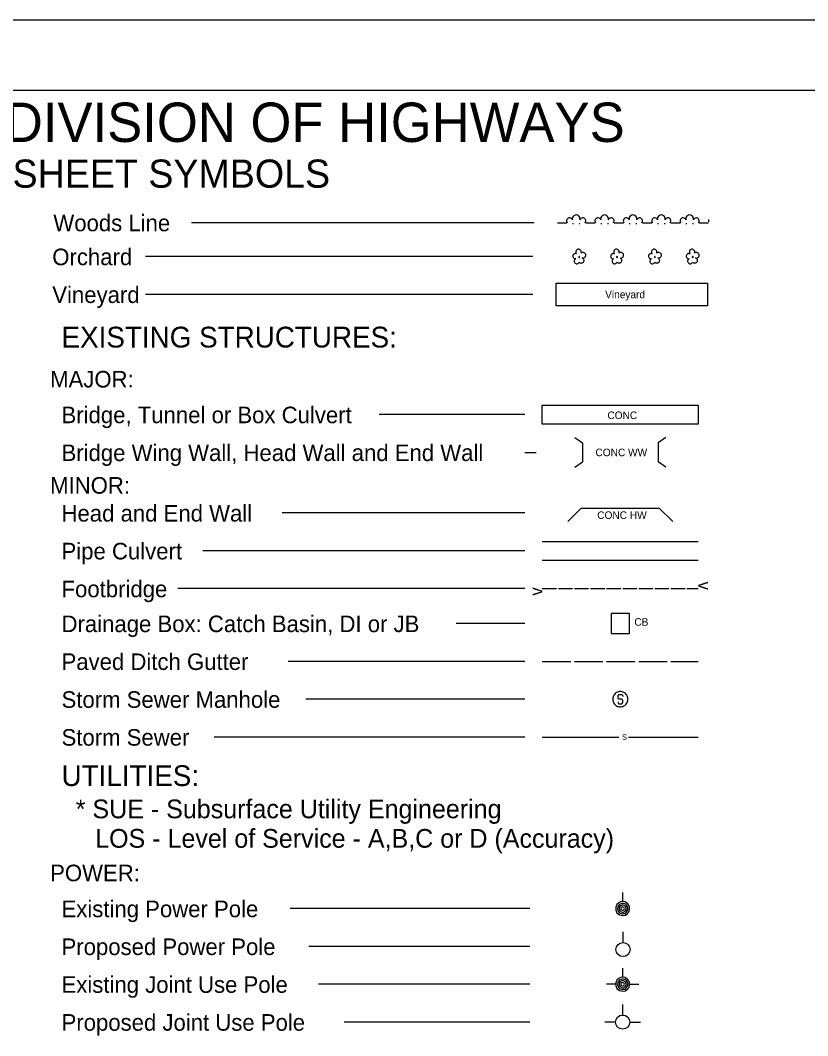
# Model space of a CAD drawing. Extents: x 2040834 to 2047174, y 618431 to 621625.
# Drawn here: x 2046085 to 2046575, y 620993 to 621625 of the extents above; entities that cross this region are included whole.
import ezdxf

# ---------------------------------------------------------------- set-up
doc = ezdxf.new("R2010")
doc.units = 0
doc.layers.add('Default', color=7, linetype='Continuous')

msp = doc.modelspace()

# ---------------------------------------------------------------- linework, layer by layer
at = {"layer": 'Default'}
for p, q in [((2047057.71, 621624.54), (2045074.38, 621624.54)), ((2047013.96, 621580.79), (2045118.13, 621580.79)), ((2046404.35, 621498.62), (2046191.15, 621498.62)), ((2046418.94, 621498.62), (2046424.82, 621498.62)), ((2046428.29, 621498.03), (2046428.88, 621498.03)), ((2046432.41, 621498.03), (2046433, 621498.03)), ((2046436.59, 621498.62), (2046442.48, 621498.62)), ((2046445.95, 621498.03), (2046446.54, 621498.03)), ((2046450.07, 621498.03), (2046450.66, 621498.03)), ((2046454.25, 621498.62), (2046460.13, 621498.62)), ((2046463.61, 621498.03), (2046464.2, 621498.03)), ((2046467.73, 621498.03), (2046468.32, 621498.03)), ((2046471.91, 621498.62), (2046477.79, 621498.62)), ((2046481.26, 621498.03), (2046481.85, 621498.03)), ((2046485.38, 621498.03), (2046485.97, 621498.03)), ((2046489.56, 621498.62), (2046495.45, 621498.62)), ((2046498.92, 621498.03), (2046499.51, 621498.03)), ((2046503.04, 621498.03), (2046503.63, 621498.03)), ((2046507.22, 621498.62), (2046513.1, 621498.62)), ((2046403.68, 621477.52), (2046162.45, 621477.52)), ((2046403.68, 621453.97), (2046162.45, 621453.97)), ((2046398.6, 621379.22), (2046308.01, 621379.22)), ((2046429.74, 621364.93), (2046434.56, 621361.56)), ((2046486.47, 621364.93), (2046481.65, 621361.56)), ((2046434.56, 621361.56), (2046434.56, 621349.79)), ((2046481.65, 621361.56), (2046481.65, 621349.79)), ((2046398.6, 621355.68), (2046405.65, 621355.68)), ((2046429.74, 621346.42), (2046434.56, 621349.79)), ((2046486.47, 621346.42), (2046481.65, 621349.79)), ((2046425.5, 621312.63), (2046433.83, 621320.96)), ((2046433.83, 621320.96), (2046482.38, 621320.96)), ((2046482.38, 621320.96), (2046490.71, 621312.63)), ((2046398.6, 621318.02), (2046247.58, 621318.02)), ((2046409.55, 621300.36), (2046506.66, 621300.36)), ((2046398.6, 621294.48), (2046198.28, 621294.48)), ((2046409.55, 621288.59), (2046506.66, 621288.59)), ((2046398.6, 621270.94), (2046182.64, 621270.94)), ((2046409.55, 621270.94), (2046418.38, 621270.94)), ((2046419.56, 621270.94), (2046428.38, 621270.94)), ((2046429.56, 621270.94), (2046438.39, 621270.94)), ((2046439.57, 621270.94), (2046448.4, 621270.94)), ((2046449.57, 621270.94), (2046458.4, 621270.94)), ((2046459.58, 621270.94), (2046468.41, 621270.94)), ((2046469.58, 621270.94), (2046478.41, 621270.94)), ((2046479.59, 621270.94), (2046488.42, 621270.94)), ((2046489.59, 621270.94), (2046498.42, 621270.94)), ((2046499.6, 621270.94), (2046506.66, 621270.94)), ((2046398.6, 621249.23), (2046355.88, 621249.23)), ((2046398.6, 621225.69), (2046251.25, 621225.69)), ((2046409.55, 621225.69), (2046427.21, 621225.69)), ((2046429.56, 621225.69), (2046447.22, 621225.69)), ((2046449.57, 621225.69), (2046467.23, 621225.69)), ((2046469.58, 621225.69), (2046487.24, 621225.69)), ((2046489.59, 621225.69), (2046506.66, 621225.69)), ((2046457.53, 621205.09), (2046458.79, 621205.09)), ((2046398.6, 621202.15), (2046262.44, 621202.15)), ((2046456.69, 621202.99), (2046456.69, 621204.25)), ((2046456.69, 621200.51), (2046456.69, 621200.08)), ((2046458.79, 621202.19), (2046457.53, 621202.19)), ((2046457.53, 621199.28), (2046458.79, 621199.28)), ((2046459.6, 621204.25), (2046459.6, 621203.83)), ((2046459.6, 621200.08), (2046459.6, 621201.38)), ((2046398.6, 621178.61), (2046205.33, 621178.61)), ((2046409.55, 621178.61), (2046457.25, 621178.61)), ((2046463.14, 621178.61), (2046506.66, 621178.61)), ((2046459.58, 621076.21), (2046459.58, 621081.86)), ((2046401.89, 621071.87), (2046252.55, 621071.87)), ((2046459.83, 621050.81), (2046459.83, 621057.43)), ((2046401.89, 621048.33), (2046264.19, 621048.33)), ((2046459.58, 621029.13), (2046459.58, 621034.78)), ((2046401.89, 621024.78), (2046270.15, 621024.78)), ((2046455.23, 621024.78), (2046449.58, 621024.78)), ((2046463.92, 621024.78), (2046469.57, 621024.78)), ((2046459.58, 621005.67), (2046459.58, 621012.29)), ((2046401.89, 621001.24), (2046286.27, 621001.24)), ((2046455.16, 621001.26), (2046448.54, 621001.26)), ((2046463.99, 621001.26), (2046470.61, 621001.26))]:
    msp.add_line(p, q, dxfattribs=at)
for points in [[(2046433.63, 621479.58), (2046433.81, 621479.93), (2046433.87, 621480.28), (2046433.81, 621480.63), (2046433.75, 621480.99), (2046433.57, 621481.28), (2046433.4, 621481.58), (2046433.1, 621481.81), (2046432.81, 621481.99), (2046432.4, 621482.11), (2046432.1, 621482.11), (2046431.75, 621482.05), (2046431.4, 621481.93), (2046431.1, 621481.75), (2046430.81, 621481.52), (2046430.63, 621481.16), (2046430.51, 621480.87), (2046430.45, 621480.52), (2046430.45, 621480.16), (2046430.51, 621479.81), (2046430.69, 621479.52), (2046430.92, 621479.16), (2046430.63, 621479.34), (2046430.28, 621479.4), (2046429.92, 621479.4), (2046429.63, 621479.28), (2046429.34, 621479.16), (2046429.04, 621478.93), (2046428.81, 621478.69), (2046428.63, 621478.4), (2046428.57, 621478.1), (2046428.51, 621477.69), (2046428.57, 621477.4), (2046428.69, 621477.1), (2046428.92, 621476.81), (2046429.1, 621476.57), (2046429.39, 621476.4), (2046429.75, 621476.22), (2046430.04, 621476.16), (2046430.4, 621476.16), (2046430.1, 621476.04), (2046429.81, 621475.81), (2046429.63, 621475.57), (2046429.51, 621475.22), (2046429.39, 621474.87), (2046429.39, 621474.57), (2046429.45, 621474.22), (2046429.63, 621473.93), (2046429.81, 621473.63), (2046430.04, 621473.4), (2046430.34, 621473.22), (2046430.63, 621473.1), (2046430.98, 621473.1), (2046431.34, 621473.1), (2046431.63, 621473.16), (2046431.93, 621473.4), (2046432.22, 621473.57), (2046432.51, 621474.1)], [(2046432.63, 621477.52), (2046432.46, 621477.52), (2046432.34, 621477.46), (2046432.22, 621477.4), (2046432.22, 621477.22), (2046432.22, 621477.1), (2046432.34, 621476.99), (2046432.51, 621476.99), (2046432.63, 621476.99), (2046432.75, 621477.1), (2046432.81, 621477.28), (2046432.75, 621477.4), (2046432.63, 621477.52)], [(2046432.51, 621474.1), (2046433.22, 621473.69), (2046433.57, 621473.57), (2046433.93, 621473.51), (2046434.28, 621473.57), (2046434.57, 621473.69), (2046434.87, 621473.87), (2046435.16, 621474.1), (2046435.34, 621474.4), (2046435.46, 621474.69), (2046435.57, 621475.04), (2046435.52, 621475.4), (2046435.46, 621475.75), (2046435.22, 621476.1), (2046435.04, 621476.34), (2046434.75, 621476.51), (2046434.4, 621476.69), (2046434.75, 621476.63), (2046435.16, 621476.63), (2046435.46, 621476.75), (2046435.81, 621476.93), (2046436.1, 621477.1), (2046436.34, 621477.4), (2046436.52, 621477.75), (2046436.57, 621478.1), (2046436.63, 621478.46), (2046436.57, 621478.81), (2046436.46, 621479.16), (2046436.22, 621479.46), (2046435.93, 621479.75), (2046435.63, 621479.93), (2046435.28, 621480.05), (2046434.93, 621480.11), (2046434.57, 621480.11), (2046434.22, 621479.99), (2046433.93, 621479.81), (2046433.63, 621479.58)], [(2046457.17, 621479.58), (2046457.35, 621479.93), (2046457.41, 621480.28), (2046457.35, 621480.63), (2046457.29, 621480.99), (2046457.12, 621481.28), (2046456.94, 621481.58), (2046456.64, 621481.81), (2046456.35, 621481.99), (2046455.94, 621482.11), (2046455.64, 621482.11), (2046455.29, 621482.05), (2046454.94, 621481.93), (2046454.64, 621481.75), (2046454.35, 621481.52), (2046454.17, 621481.16), (2046454.05, 621480.87), (2046454, 621480.52), (2046454, 621480.16), (2046454.05, 621479.81), (2046454.23, 621479.52), (2046454.47, 621479.16), (2046454.17, 621479.34), (2046453.82, 621479.4), (2046453.47, 621479.4), (2046453.17, 621479.28), (2046452.88, 621479.16), (2046452.58, 621478.93), (2046452.35, 621478.69), (2046452.17, 621478.4), (2046452.11, 621478.1), (2046452.05, 621477.69), (2046452.11, 621477.4), (2046452.23, 621477.1), (2046452.47, 621476.81), (2046452.64, 621476.57), (2046452.94, 621476.4), (2046453.29, 621476.22), (2046453.58, 621476.16), (2046453.94, 621476.16), (2046453.64, 621476.04), (2046453.35, 621475.81), (2046453.17, 621475.57), (2046453.05, 621475.22), (2046452.94, 621474.87), (2046452.94, 621474.57), (2046453, 621474.22), (2046453.17, 621473.93), (2046453.35, 621473.63), (2046453.58, 621473.4), (2046453.88, 621473.22), (2046454.17, 621473.1), (2046454.53, 621473.1), (2046454.88, 621473.1), (2046455.17, 621473.16), (2046455.47, 621473.4), (2046455.76, 621473.57), (2046456.06, 621474.1)], [(2046456.17, 621477.52), (2046456, 621477.52), (2046455.88, 621477.46), (2046455.76, 621477.4), (2046455.76, 621477.22), (2046455.76, 621477.1), (2046455.88, 621476.99), (2046456.06, 621476.99), (2046456.17, 621476.99), (2046456.29, 621477.1), (2046456.35, 621477.28), (2046456.29, 621477.4), (2046456.17, 621477.52)], [(2046456.06, 621474.1), (2046456.76, 621473.69), (2046457.12, 621473.57), (2046457.47, 621473.51), (2046457.82, 621473.57), (2046458.12, 621473.69), (2046458.41, 621473.87), (2046458.7, 621474.1), (2046458.88, 621474.4), (2046459, 621474.69), (2046459.12, 621475.04), (2046459.06, 621475.4), (2046459, 621475.75), (2046458.76, 621476.1), (2046458.59, 621476.34), (2046458.29, 621476.51), (2046457.94, 621476.69), (2046458.29, 621476.63), (2046458.7, 621476.63), (2046459, 621476.75), (2046459.35, 621476.93), (2046459.65, 621477.1), (2046459.88, 621477.4), (2046460.06, 621477.75), (2046460.12, 621478.1), (2046460.18, 621478.46), (2046460.12, 621478.81), (2046460, 621479.16), (2046459.76, 621479.46), (2046459.47, 621479.75), (2046459.18, 621479.93), (2046458.82, 621480.05), (2046458.47, 621480.11), (2046458.12, 621480.11), (2046457.76, 621479.99), (2046457.47, 621479.81), (2046457.17, 621479.58)], [(2046480.72, 621479.58), (2046480.89, 621479.93), (2046480.95, 621480.28), (2046480.89, 621480.63), (2046480.83, 621480.99), (2046480.66, 621481.28), (2046480.48, 621481.58), (2046480.19, 621481.81), (2046479.89, 621481.99), (2046479.48, 621482.11), (2046479.19, 621482.11), (2046478.83, 621482.05), (2046478.48, 621481.93), (2046478.19, 621481.75), (2046477.89, 621481.52), (2046477.71, 621481.16), (2046477.6, 621480.87), (2046477.54, 621480.52), (2046477.54, 621480.16), (2046477.6, 621479.81), (2046477.77, 621479.52), (2046478.01, 621479.16), (2046477.71, 621479.34), (2046477.36, 621479.4), (2046477.01, 621479.4), (2046476.71, 621479.28), (2046476.42, 621479.16), (2046476.13, 621478.93), (2046475.89, 621478.69), (2046475.71, 621478.4), (2046475.65, 621478.1), (2046475.6, 621477.69), (2046475.65, 621477.4), (2046475.77, 621477.1), (2046476.01, 621476.81), (2046476.18, 621476.57), (2046476.48, 621476.4), (2046476.83, 621476.22), (2046477.13, 621476.16), (2046477.48, 621476.16), (2046477.18, 621476.04), (2046476.89, 621475.81), (2046476.71, 621475.57), (2046476.6, 621475.22), (2046476.48, 621474.87), (2046476.48, 621474.57), (2046476.54, 621474.22), (2046476.71, 621473.93), (2046476.89, 621473.63), (2046477.13, 621473.4), (2046477.42, 621473.22), (2046477.71, 621473.1), (2046478.07, 621473.1), (2046478.42, 621473.1), (2046478.71, 621473.16), (2046479.01, 621473.4), (2046479.3, 621473.57), (2046479.6, 621474.1)], [(2046479.72, 621477.52), (2046479.54, 621477.52), (2046479.42, 621477.46), (2046479.3, 621477.4), (2046479.3, 621477.22), (2046479.3, 621477.1), (2046479.42, 621476.99), (2046479.6, 621476.99), (2046479.72, 621476.99), (2046479.83, 621477.1), (2046479.89, 621477.28), (2046479.83, 621477.4), (2046479.72, 621477.52)], [(2046479.6, 621474.1), (2046480.3, 621473.69), (2046480.66, 621473.57), (2046481.01, 621473.51), (2046481.36, 621473.57), (2046481.66, 621473.69), (2046481.95, 621473.87), (2046482.25, 621474.1), (2046482.42, 621474.4), (2046482.54, 621474.69), (2046482.66, 621475.04), (2046482.6, 621475.4), (2046482.54, 621475.75), (2046482.3, 621476.1), (2046482.13, 621476.34), (2046481.83, 621476.51), (2046481.48, 621476.69), (2046481.83, 621476.63), (2046482.25, 621476.63), (2046482.54, 621476.75), (2046482.89, 621476.93), (2046483.19, 621477.1), (2046483.42, 621477.4), (2046483.6, 621477.75), (2046483.66, 621478.1), (2046483.72, 621478.46), (2046483.66, 621478.81), (2046483.54, 621479.16), (2046483.31, 621479.46), (2046483.01, 621479.75), (2046482.72, 621479.93), (2046482.36, 621480.05), (2046482.01, 621480.11), (2046481.66, 621480.11), (2046481.3, 621479.99), (2046481.01, 621479.81), (2046480.72, 621479.58)], [(2046504.26, 621479.58), (2046504.43, 621479.93), (2046504.49, 621480.28), (2046504.43, 621480.63), (2046504.38, 621480.99), (2046504.2, 621481.28), (2046504.02, 621481.58), (2046503.73, 621481.81), (2046503.43, 621481.99), (2046503.02, 621482.11), (2046502.73, 621482.11), (2046502.37, 621482.05), (2046502.02, 621481.93), (2046501.73, 621481.75), (2046501.43, 621481.52), (2046501.26, 621481.16), (2046501.14, 621480.87), (2046501.08, 621480.52), (2046501.08, 621480.16), (2046501.14, 621479.81), (2046501.32, 621479.52), (2046501.55, 621479.16), (2046501.26, 621479.34), (2046500.9, 621479.4), (2046500.55, 621479.4), (2046500.26, 621479.28), (2046499.96, 621479.16), (2046499.67, 621478.93), (2046499.43, 621478.69), (2046499.26, 621478.4), (2046499.2, 621478.1), (2046499.14, 621477.69), (2046499.2, 621477.4), (2046499.31, 621477.1), (2046499.55, 621476.81), (2046499.73, 621476.57), (2046500.02, 621476.4), (2046500.37, 621476.22), (2046500.67, 621476.16), (2046501.02, 621476.16), (2046500.73, 621476.04), (2046500.43, 621475.81), (2046500.26, 621475.57), (2046500.14, 621475.22), (2046500.02, 621474.87), (2046500.02, 621474.57), (2046500.08, 621474.22), (2046500.26, 621473.93), (2046500.43, 621473.63), (2046500.67, 621473.4), (2046500.96, 621473.22), (2046501.26, 621473.1), (2046501.61, 621473.1), (2046501.96, 621473.1), (2046502.26, 621473.16), (2046502.55, 621473.4), (2046502.85, 621473.57), (2046503.14, 621474.1)], [(2046503.26, 621477.52), (2046503.08, 621477.52), (2046502.96, 621477.46), (2046502.85, 621477.4), (2046502.85, 621477.22), (2046502.85, 621477.1), (2046502.96, 621476.99), (2046503.14, 621476.99), (2046503.26, 621476.99), (2046503.37, 621477.1), (2046503.43, 621477.28), (2046503.37, 621477.4), (2046503.26, 621477.52)], [(2046503.14, 621474.1), (2046503.85, 621473.69), (2046504.2, 621473.57), (2046504.55, 621473.51), (2046504.91, 621473.57), (2046505.2, 621473.69), (2046505.49, 621473.87), (2046505.79, 621474.1), (2046505.96, 621474.4), (2046506.08, 621474.69), (2046506.2, 621475.04), (2046506.14, 621475.4), (2046506.08, 621475.75), (2046505.85, 621476.1), (2046505.67, 621476.34), (2046505.38, 621476.51), (2046505.02, 621476.69), (2046505.38, 621476.63), (2046505.79, 621476.63), (2046506.08, 621476.75), (2046506.44, 621476.93), (2046506.73, 621477.1), (2046506.97, 621477.4), (2046507.14, 621477.75), (2046507.2, 621478.1), (2046507.26, 621478.46), (2046507.2, 621478.81), (2046507.08, 621479.16), (2046506.85, 621479.46), (2046506.55, 621479.75), (2046506.26, 621479.93), (2046505.91, 621480.05), (2046505.55, 621480.11), (2046505.2, 621480.11), (2046504.85, 621479.99), (2046504.55, 621479.81), (2046504.26, 621479.58)], [(2046418.27, 621461.04), (2046512.44, 621461.04), (2046512.44, 621446.91), (2046418.27, 621446.91), (2046418.27, 621461.04)], [(2046409.55, 621385.11), (2046506.66, 621385.11), (2046506.66, 621373.34), (2046409.55, 621373.34), (2046409.55, 621385.11)], [(2046458.11, 621206.93), (2046457.49, 621206.89), (2046456.92, 621206.78), (2046456.35, 621206.58), (2046455.81, 621206.32), (2046455.32, 621206.01), (2046454.86, 621205.63), (2046454.43, 621205.17), (2046454.09, 621204.71), (2046453.79, 621204.18), (2046453.59, 621203.6), (2046453.44, 621203.03), (2046453.37, 621202.46), (2046453.37, 621201.84), (2046453.44, 621201.27), (2046453.59, 621200.66), (2046453.79, 621200.12), (2046454.09, 621199.59), (2046454.43, 621199.13), (2046454.86, 621198.67), (2046455.32, 621198.29), (2046455.81, 621197.98), (2046456.35, 621197.71), (2046456.92, 621197.52), (2046457.53, 621197.41), (2046458.11, 621197.37), (2046458.72, 621197.41), (2046459.29, 621197.52), (2046459.87, 621197.71), (2046460.4, 621197.98), (2046460.9, 621198.29), (2046461.36, 621198.67), (2046461.78, 621199.13), (2046462.12, 621199.59), (2046462.43, 621200.12), (2046462.62, 621200.7), (2046462.77, 621201.27), (2046462.85, 621201.84), (2046462.85, 621202.46), (2046462.77, 621203.03), (2046462.62, 621203.64), (2046462.43, 621204.18), (2046462.12, 621204.71), (2046461.78, 621205.17), (2046461.36, 621205.63), (2046460.9, 621206.01), (2046460.4, 621206.32), (2046459.87, 621206.58), (2046459.29, 621206.78), (2046458.68, 621206.89), (2046458.11, 621206.93)], [(2046456.69, 621204.25), (2046456.77, 621204.52), (2046456.88, 621204.75), (2046457.04, 621204.9), (2046457.27, 621205.02), (2046457.53, 621205.09)], [(2046458.79, 621205.09), (2046459.02, 621205.02), (2046459.25, 621204.9), (2046459.44, 621204.75), (2046459.56, 621204.52), (2046459.6, 621204.25)], [(2046457.53, 621202.19), (2046457.27, 621202.23), (2046457.04, 621202.34), (2046456.88, 621202.53), (2046456.77, 621202.76), (2046456.69, 621202.99)], [(2046456.69, 621200.12), (2046456.77, 621199.86), (2046456.88, 621199.63), (2046457.04, 621199.43), (2046457.27, 621199.32), (2046457.53, 621199.28)], [(2046459.6, 621201.35), (2046459.56, 621201.61), (2046459.44, 621201.84), (2046459.25, 621202.03), (2046459.02, 621202.15), (2046458.79, 621202.19)], [(2046458.79, 621199.28), (2046459.02, 621199.32), (2046459.25, 621199.43), (2046459.44, 621199.63), (2046459.56, 621199.86), (2046459.6, 621200.12)], [(2046462.79, 621071.87), (2046462.71, 621072.65), (2046462.44, 621073.34), (2046462.01, 621073.95), (2046461.49, 621074.47), (2046460.88, 621074.82), (2046460.1, 621075), (2046459.4, 621075.08), (2046458.62, 621074.91), (2046457.93, 621074.65), (2046457.41, 621074.21), (2046456.89, 621073.6), (2046456.54, 621073), (2046456.36, 621072.21), (2046456.36, 621071.52), (2046456.54, 621070.74), (2046456.89, 621070.13), (2046457.41, 621069.52), (2046457.93, 621069.09), (2046458.62, 621068.83), (2046459.4, 621068.65), (2046460.1, 621068.74), (2046460.88, 621068.91), (2046461.49, 621069.26), (2046462.01, 621069.78), (2046462.44, 621070.39), (2046462.71, 621071.09), (2046462.79, 621071.87)], [(2046461.75, 621071.87), (2046461.66, 621072.48), (2046461.4, 621073.08), (2046460.97, 621073.52), (2046460.45, 621073.87), (2046459.93, 621074.04), (2046459.23, 621074.04), (2046458.71, 621073.87), (2046458.19, 621073.52), (2046457.75, 621073.08), (2046457.49, 621072.48), (2046457.41, 621071.87), (2046457.49, 621071.26), (2046457.75, 621070.65), (2046458.19, 621070.22), (2046458.71, 621069.87), (2046459.23, 621069.7), (2046459.93, 621069.7), (2046460.45, 621069.87), (2046460.97, 621070.22), (2046461.4, 621070.65), (2046461.66, 621071.26), (2046461.75, 621071.87)], [(2046460.62, 621071.87), (2046460.53, 621072.3), (2046460.27, 621072.65), (2046459.93, 621072.82), (2046459.49, 621072.91), (2046459.06, 621072.74), (2046458.71, 621072.48), (2046458.53, 621072.04), (2046458.53, 621071.69), (2046458.71, 621071.26), (2046459.06, 621071), (2046459.49, 621070.82), (2046459.93, 621070.91), (2046460.27, 621071.09), (2046460.53, 621071.43), (2046460.62, 621071.87)], [(2046462.79, 621024.78), (2046462.71, 621025.56), (2046462.44, 621026.26), (2046462.01, 621026.87), (2046461.49, 621027.39), (2046460.88, 621027.74), (2046460.1, 621027.91), (2046459.4, 621028), (2046458.62, 621027.83), (2046457.93, 621027.56), (2046457.41, 621027.13), (2046456.89, 621026.52), (2046456.54, 621025.91), (2046456.36, 621025.13), (2046456.36, 621024.44), (2046456.54, 621023.65), (2046456.89, 621023.05), (2046457.41, 621022.44), (2046457.93, 621022), (2046458.62, 621021.74), (2046459.4, 621021.57), (2046460.1, 621021.66), (2046460.88, 621021.83), (2046461.49, 621022.18), (2046462.01, 621022.7), (2046462.44, 621023.31), (2046462.71, 621024), (2046462.79, 621024.78)], [(2046461.75, 621024.78), (2046461.66, 621025.39), (2046461.4, 621026), (2046460.97, 621026.43), (2046460.45, 621026.78), (2046459.93, 621026.95), (2046459.23, 621026.95), (2046458.71, 621026.78), (2046458.19, 621026.43), (2046457.75, 621026), (2046457.49, 621025.39), (2046457.41, 621024.78), (2046457.49, 621024.17), (2046457.75, 621023.57), (2046458.19, 621023.13), (2046458.71, 621022.78), (2046459.23, 621022.61), (2046459.93, 621022.61), (2046460.45, 621022.78), (2046460.97, 621023.13), (2046461.4, 621023.57), (2046461.66, 621024.17), (2046461.75, 621024.78)], [(2046460.62, 621024.78), (2046460.53, 621025.22), (2046460.27, 621025.56), (2046459.93, 621025.74), (2046459.49, 621025.83), (2046459.06, 621025.65), (2046458.71, 621025.39), (2046458.53, 621024.96), (2046458.53, 621024.61), (2046458.71, 621024.17), (2046459.06, 621023.91), (2046459.49, 621023.74), (2046459.93, 621023.83), (2046460.27, 621024), (2046460.53, 621024.35), (2046460.62, 621024.78)]]:
    msp.add_lwpolyline(points, dxfattribs=at)
for points in [[(2046452.44, 621242.98), (2046463.76, 621242.98), (2046463.76, 621255.5), (2046452.44, 621255.5)], [(2046459.58, 621067.52), (2046461.4, 621067.87), (2046462.62, 621068.74), (2046463.58, 621069.96), (2046463.92, 621071.61), (2046463.75, 621073.17), (2046462.88, 621074.73), (2046461.14, 621076.04), (2046459.14, 621076.21), (2046457.41, 621075.69), (2046456.02, 621074.47), (2046455.32, 621072.82), (2046455.32, 621070.91), (2046456.02, 621069.26), (2046457.58, 621067.96)], [(2046459.58, 621020.44), (2046461.4, 621020.79), (2046462.62, 621021.66), (2046463.58, 621022.87), (2046463.92, 621024.52), (2046463.75, 621026.09), (2046462.88, 621027.65), (2046461.14, 621028.95), (2046459.14, 621029.13), (2046457.41, 621028.61), (2046456.02, 621027.39), (2046455.32, 621025.74), (2046455.32, 621023.83), (2046456.02, 621022.18), (2046457.58, 621020.87)]]:
    msp.add_lwpolyline(points, close=True, dxfattribs=at)
for centre in [(2046459.83, 621046.4), (2046459.58, 621001.24)]:
    msp.add_circle(centre, 4.41, dxfattribs=at)
for centre, radius, start, end in [((2046430.65, 621500.99), 2.43, 345.96376, 194.03624), ((2046448.3, 621500.99), 2.43, 345.96376, 194.03624), ((2046465.96, 621500.99), 2.43, 345.96376, 194.03624), ((2046483.61, 621500.99), 2.43, 345.96376, 194.03624), ((2046501.27, 621500.99), 2.43, 345.96376, 194.03624), ((2046426.53, 621499.81), 1.86, 18.43495, 219.23152), ((2046434.77, 621499.81), 1.86, 320.76848, 161.56505), ((2046444.18, 621499.81), 1.86, 18.43495, 219.23152), ((2046452.42, 621499.81), 1.86, 320.76848, 161.56505), ((2046461.84, 621499.81), 1.86, 18.43495, 219.23152), ((2046470.08, 621499.81), 1.86, 320.76848, 161.56505), ((2046479.49, 621499.81), 1.86, 18.43495, 219.23152), ((2046487.73, 621499.81), 1.86, 320.76848, 161.56505), ((2046497.15, 621499.81), 1.86, 18.43495, 219.23152), ((2046505.39, 621499.81), 1.86, 320.76848, 161.56505), ((2046514.81, 621499.81), 1.86, 156.25102, 203.74899)]:
    msp.add_arc(centre, radius, start, end, dxfattribs=at)

# ---------------------------------------------------------------- texts
for s, height, p in [('STATE OF NORTH CAROLINA, DIVISION OF HIGHWAYS', 24.5, (2045594.41, 621548.84)), ('CONVENTIONAL  PLAN SHEET SYMBOLS', 17.5, (2045814.5, 621520.41)), ('Woods Line', 10.3, (2046105.18, 621493.29)), ('Orchard', 10.3, (2046104.51, 621472.19)), ('Vineyard', 10.3, (2046104.51, 621448.65)), ('EXISTING STRUCTURES:', 12.9481, (2046110.26, 621420.95)), ('MAJOR:', 10.3, (2046103.17, 621396.1)), ('Bridge, Tunnel or Box Culvert', 10.2996, (2046110.26, 621373.87)), ('CONC', 4.708, (2046450.09, 621376.44)), ('Bridge Wing Wall, Head Wall and End Wall', 10.2996, (2046110.26, 621350.32)), ('MINOR:', 10.3, (2046103.17, 621330.03)), ('Head and End Wall', 10.2996, (2046110.26, 621312.66)), ('Pipe Culvert', 10.2996, (2046110.26, 621289.14)), ('Footbridge', 10.3, (2046110.27, 621265.59)), ('Drainage Box: Catch Basin, DI or JB', 10.2996, (2046110.27, 621243.89)), ('Paved Ditch Gutter', 10.2996, (2046110.27, 621220.34)), ('Storm Sewer Manhole', 10.2996, (2046110.27, 621196.79)), ('Storm Sewer', 10.2996, (2046110.27, 621173.25)), ('S', 3.53, (2046459.14, 621176.84)), ('UTILITIES:', 12.948, (2046110.26, 621148.1)), ('POWER:', 10.3, (2046103.17, 621088.89)), ('Existing Power Pole', 10.2996, (2046110.27, 621066.53)), ('Proposed Power Pole', 10.2996, (2046110.27, 621042.98)), ('Existing Joint Use Pole', 10.2996, (2046110.27, 621019.46)), ('Proposed Joint Use Pole', 10.2996, (2046110.29, 620995.9))]:
    msp.add_text(s, height=height, dxfattribs=at).set_placement(p)
for s, height, rotation, p in [('Vineyard', 4.708, 0.00002, (2046448.67, 621451.62)), ('CONC WW', 4.708, 0.00002, (2046442.66, 621353.33)), ('CONC HW', 4.708, 360, (2046443.75, 621314.3)), ('v', 7.77, 270.24085, (2046506.65, 621275.33)), ('v', 7.77, 89.75915, (2046409.54, 621266.54)), ('CB', 4.708, 360, (2046466.86, 621247.85)), ('* SUE - Subsurface Utility Engineering', 11.6533, 360, (2046119.13, 621128.07)), ('LOS - Level of Service - A,B,C or D (Accuracy) ', 11.6533, 360, (2046131.22, 621109.74))]:
    msp.add_text(s, height=height, rotation=rotation, dxfattribs=at).set_placement(p)

doc.saveas('drawing.dxf')
